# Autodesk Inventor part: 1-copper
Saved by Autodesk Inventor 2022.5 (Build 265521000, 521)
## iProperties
Created: 2024-07
Part Number: 1-copper
Material: Generic
Document SubType Name: Modeling
Designer: AdminForWorker
Density: 1 g/cm^3
Appearance: Default
Title: 1-copper
Author: AdminForWorker
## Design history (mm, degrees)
feature "Body1"
feature "Body3"
feature "Body2"
body "Solid1"
body "Solid2"
body "Solid3"
